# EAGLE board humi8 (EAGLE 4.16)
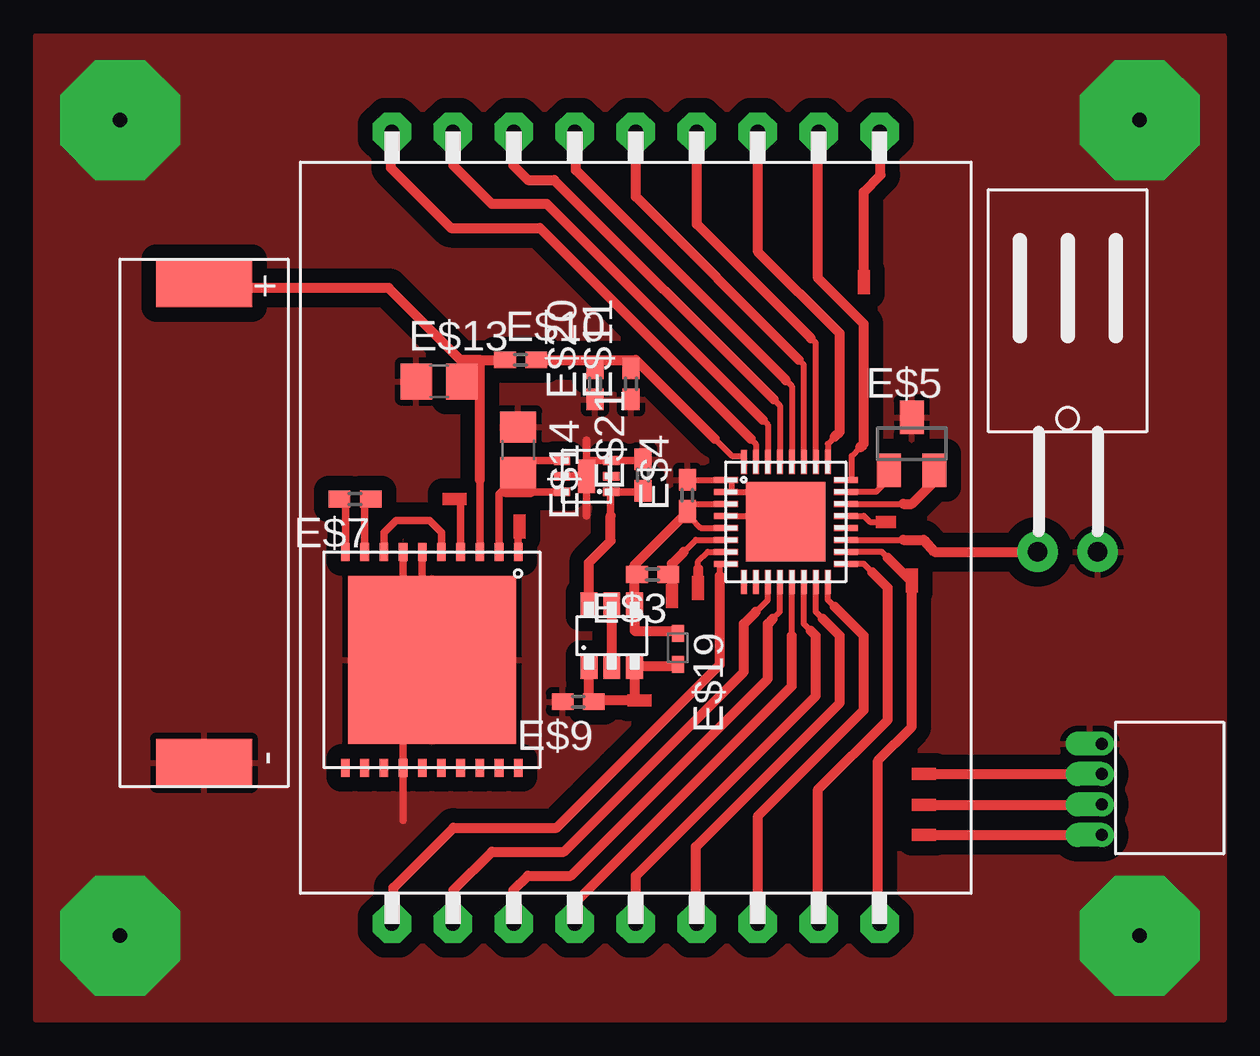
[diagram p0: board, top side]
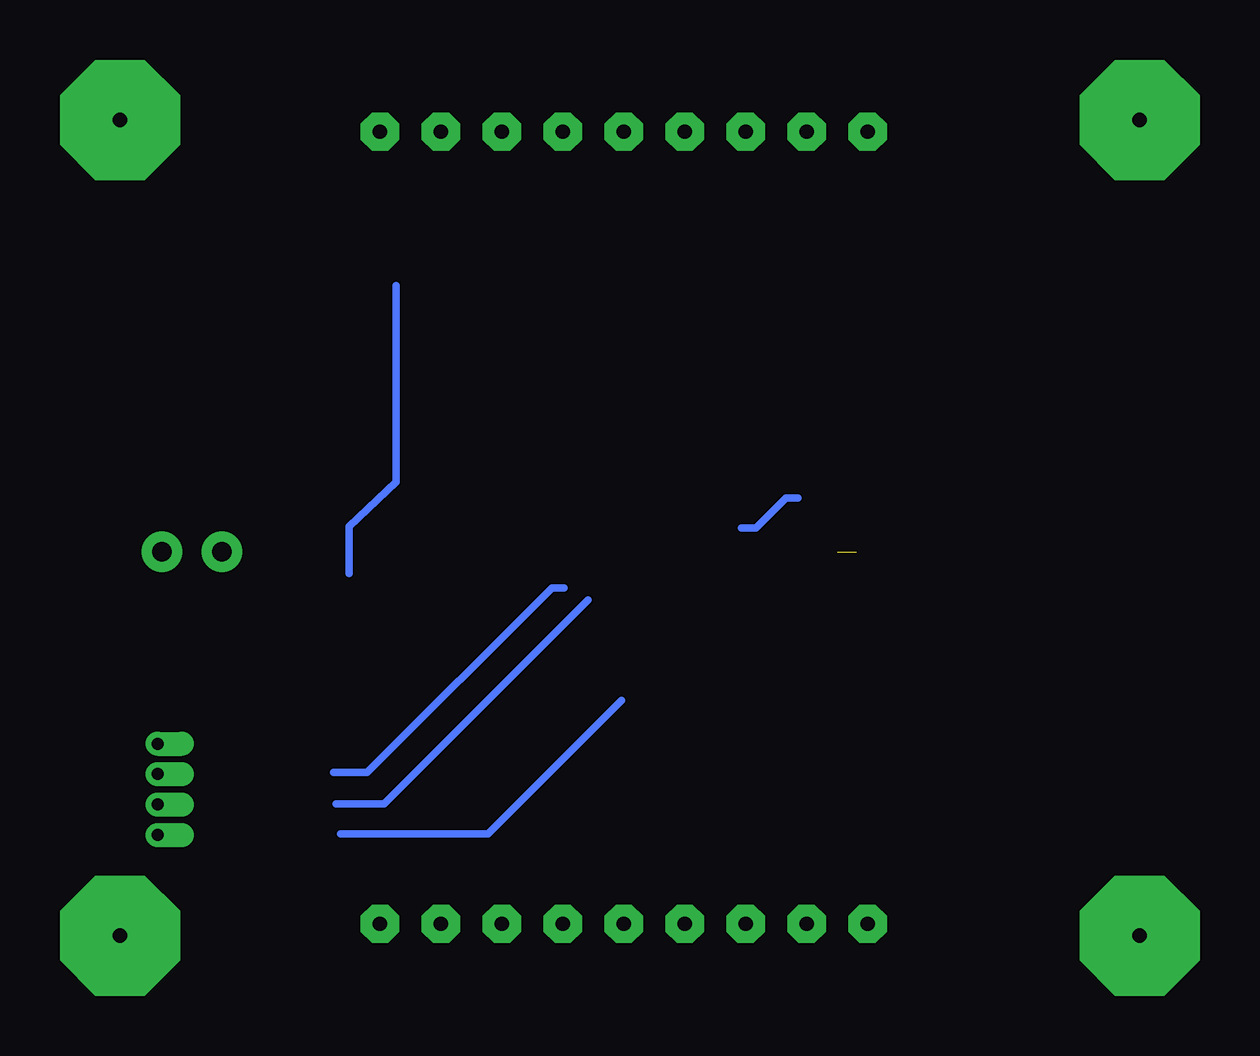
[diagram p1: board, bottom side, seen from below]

No outline drawn. Coordinates in mm, seen from the top.
Copper layers (1*16): Top 0.035mm / dielectric 1.5mm / Bottom 0.035mm
Design rules "default": minimum track width 10mil, minimum drill 24mil, track to track 8mil, track to pad 8mil, pad to pad 8mil, via to via 8mil, smd to smd 8mil, copper to edge 40mil, drill to drill 8mil, minimum pad ring 10mil, minimum via ring 8mil, stop-mask expansion 4mil, vias tented up to drill 0mil, thermal gap 10mil

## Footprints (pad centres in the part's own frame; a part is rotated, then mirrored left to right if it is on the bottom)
QFN32 = smd 1 x 0.25: P$1 -2.25,2; P$2 -2.25,1.5; P$3 -2.25,1; P$4 -2.25,0.5; P$5 -2.25,0; P$6 -2.25,-0.5; P$7 -2.25,-1; P$8 -2.25,-1.5; P$17 2.75,-1.5; P$18 2.75,-1; P$19 2.75,-0.5; P$20 2.75,0; P$21 2.75,0.5; P$22 2.75,1; P$23 2.75,1.5; P$24 2.75,2 | smd 0.25 x 1: P$9 -1.5,-2.25; P$10 -0.5,-2.25; P$11 -1,-2.25; P$12 0,-2.25; P$13 0.5,-2.25; P$14 1,-2.25; P$15 1.5,-2.25; P$16 2,-2.25; P$25 2,2.75; P$26 1.5,2.75; P$27 1,2.75; P$28 0.5,2.75; P$29 0,2.75; P$30 -0.5,2.75; P$31 -1,2.75; P$32 -1.5,2.75 | smd 3.3 x 3.3: P$33 0.25,0.25
VI201 = drill 0.6 pad 1.6 octagon: 1 -10.16,-16.51; 2 -7.62,-16.51; 3 -5.08,-16.51; 4 -2.54,-16.51; 5 0,-16.51; 6 2.54,-16.51; 7 5.08,-16.51; 8 7.62,-16.51; 9 10.16,-16.51; 10 10.16,16.51; 11 7.62,16.51; 12 5.08,16.51; 13 2.54,16.51; 14 0,16.51; 15 -2.54,16.51; 16 -5.08,16.51; 17 -7.62,16.51; 18 -10.16,16.51
R0402 = smd 0.9 x 0.7: 1 -0.65,0; 2 0.65,0
SOT23 = smd 1 x 1.4: 1 -0.95,-1.1; 2 0.95,-1.1; 3 0,1.1
CBC3150 = smd 0.75 x 0.36: P$1 -4.5,-3.6; P$2 -4.5,-2.8; P$3 -4.5,-2; P$4 -4.5,-1.2; P$5 -4.5,-0.4; P$6 -4.5,0.4; P$7 -4.5,1.2; P$8 -4.5,2; P$9 -4.5,2.8; P$10 -4.5,3.6; P$11 4.5,-3.6; P$12 4.5,-2.8; P$13 4.5,-2; P$14 4.5,-1.2; P$15 4.5,-0.4; P$16 4.5,0.4; P$17 4.5,1.2; P$18 4.5,2; P$19 4.5,2.8; P$20 4.5,3.6 | smd 7 x 7: P$21 0,0
6UTDFN = smd 0.68 x 0.36: 1 -1.025,0.65; 2 -1.025,0; 3 -1.025,-0.65; 4 1.025,-0.65; 5 1.025,0; 6 1.025,0.65 | smd 0.71 x 1.4: 7 0,0
KXO22-01X8 = smd 2 x 4: P$1 1,3.5; P$2 21,3.5
C0805 = smd 1.3 x 1.5: 1 -0.95,0; 2 0.95,0
HCH-1000 = drill 0.8 pad 1.676 round: P$1 -1.25,-5; P$2 1.25,-5
HEADER4S_R = drill 0.5 offset: P$1 0,-1.27; P$2 1.27,-1.27; P$3 2.54,-1.27; P$4 3.81,-1.27
SUPERSOT-6 = smd 0.7 x 1: P$1 -0.95,1.3; P$2 0,1.3; P$3 0.95,1.3; P$4 -0.95,-1.3; P$5 0,-1.3; P$6 0.95,-1.3
SOD523 = smd 0.7 x 0.5: A 0.7,0; C -0.6,0

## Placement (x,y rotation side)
E$1  [QFN32]  31,20.5 0 top
E$2  [VI201]  25,20.5 180 top
E$3  [R0402]  25.7,18.55 180 top
E$4  [R0402]  27.15,21.85 90 top
E$5  [SOT23]  36.5,24 0 top
E$6  [CBC3150]  16.5,15 270 top
E$7  [R0402]  13.3,21.7 180 top
E$8  [6UTDFN]  22.95,22.65 180 top
E$9  [R0402]  22.6,13.25 180 top
E$10  [R0402]  20.2,27.5 0 top
E$11  [R0402]  24.8,26.5 90 top
E$12  [KXO22-01X8]  3.5,31.7 270 top
E$13  [C0805]  16.8,26.6 0 top
E$14  [C0805]  20.1,23.75 270 top
E$15  [HCH-1000]  43,24.5 0 top
E$16  [HEADER4S_R]  45.7,11.5 270 top
E$18  [SUPERSOT-6]  24,16 0 top
E$19  [SOD523]  26.75,15.5 270 top
E$20  [R0402]  23.3,26.5 90 top
E$21  [R0402]  25.3,22.7 90 top

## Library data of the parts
E$1 = silabs
E$2 = display-lcd
E$3 E$4 E$7 E$9-E$11 E$13 E$14 E$19-E$21 = ref-packages
E$5 = transistor-fet
E$6 = cymbet
E$8 = maxim
E$12 E$15 E$16 E$18 = sb

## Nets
GND: E$4.2 E$5.3 E$6.P$4 E$6.P$21 E$8.7 E$9.2 E$11.1 E$12.P$2 E$13.1 E$14.1 E$15.P$2 E$16.P$1 E$20.1 E$21.2
S$26: E$6.P$3
S$30: E$6.P$8

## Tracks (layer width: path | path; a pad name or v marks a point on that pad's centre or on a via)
GND  (via drill 0.6 pad 5)  (1 unrouted)
  Top 0.254: E$4.2 28.5,22.5
  Top 0.305: 16,17.9 15.3,17.9 E$6.P$4 | 16.1,19.5 16.1,13.5 15.3,13.5 15.3,8.3 | 22.95,23.3 22.95,24.15 | 22.95,23.3 25.3,23.3 | E$8.7 22.95,21 | E$8.7 22.95,23.3 | 21.95,22.65 E$8.7
  other vias: 3.5,3.5 3.5,37.5 46,3.5 46,37.5
  pour Top (isolate 0.61): 0,0 0,41 49.5,41 49.5,0
PWR
  Top 0.305: 20.65,23.3 21.75,23.3
S$1
  Top 0.254: 33.5,22.5 34,22.5 34,23.5 34.35,23.85
  Top 0.406: 34.35,23.85 34.5,24 34.5,29 32.6,30.9 32.6,37
S$2
  Top 0.254: 28.5,18.5 28.5,19
  Top 0.406: 28.5,18.5 28.5,14.8 21.7,8 17.4,8 14.9,5.5 14.9,4
S$3
  Top 0.305: 13.7,19.7 13.7,21.4
S$4
  Top 0.254: 30.3,25 30.5,24.8 30.5,23.5
  Top 0.406: 17.4,37 17.4,35.6 19,34 21.3,34 30.3,25
S$5
  Top 0.254: 31,23.5 31,25.6 30.75,25.85
  Top 0.406: 30.75,25.85 21.6,35 20.5,35 19.9,35.6 19.9,37.1
S$6
  Top 0.254: 31.5,23.5 31.5,26.4 31.25,26.65
  Top 0.406: 31.25,26.65 22.5,35.4 22.5,37
S$7
  Top 0.254: 32.5,23.5 32.5,28.2 32.3,28.4
  Top 0.406: 32.3,28.4 27.55,33.15 27.55,37
S$8
  Top 0.254: 32,23.5 32,27.3 31.8,27.5
  Top 0.406: 31.8,27.5 25,34.3 25,37
S$9
  Top 0.254: 35.5,19.25 35.25,19.5 34,19.5
  Top 0.406: 35.5,19.25 36.5,18.25
S$10
  Top 0.254: 34.85,18.65 34.5,19 34,19
  Top 0.406: 34.85,18.65 35.5,18 35.5,12.5 32.6,9.6 32.6,4
S$11
  Top 0.254: 32.3,16.2 32,16.5 32,18
  Top 0.406: 32.3,16.2 32.5,16 32.5,13.5 25,6 25,4
S$12
  Top 0.254: 30.5,18 30.5,17.5 30,17
  Top 0.406: 30,17 29.5,16.5 29.5,14.5 22,7 19,7 17.4,5.4 17.4,4
S$13
  Top 0.254: 30.7,16.7 31,17 31,18
  Top 0.406: 30.7,16.7 30.5,16.5 30.5,14.2 22.3,6 20.5,6 19.9,5.4 19.9,4
S$14
  Top 0.254: 31.5,16 31.5,18
  Top 0.406: 31.5,16 31.5,13.9 22.5,4.9 22.5,4
S$15
  Top 0.254: 34,22 35,22 35.5,22.5
S$16
  Top 0.254: 32.8,16.7 32.5,17 32.5,18
  Top 0.406: 32.8,16.7 33.5,16 33.5,13.2 27.5,7.2 27.5,4
S$17
  Top 0.254: 33,18 33,17.5 33.3,17.2
  Top 0.406: 33.3,17.2 34.5,16 34.5,12.9 30.1,8.5 30.1,4
S$18
  Top 0.254: 29,22.5 29,22 30,22
S$19
  Top 0.254: 29,21 30,21
S$20
  Top 0.254: 28.5,20.5 27.7,20.5 27.3,20.9
  Top 0.406: 27.3,20.9 26.9,20.9 24.95,18.95 24.95,17.5
S$21
  Top 0.254: 28.5,20 27.5,20 27,19.5
  Top 0.406: 26.5,17.85 26.5,19 27,19.5
S$22
  Top 0.254: 28.5,19.5 28,19.5 27.6,19.1 27.6,18.8
  Top 0.406: 27.6,18.8 27.6,18
S$23
  Top 0.254: 30,23.5 30,24 29.8,24.2
  Top 0.406: 14.8,37 14.8,35.5 17.3,33 21,33 29.8,24.2
S$24
  Top 0.305: 12.9,19.7 12.9,21.5
S$25
  Top 0.406: 35.1,4 35.1,10.8 36.5,12.2 36.5,18.25
S$26
  Top 0.305: E$6.P$3 14.5,20.3 15,20.8 16.4,20.8 16.9,20.3 16.9,19.5
S$27
  Top 0.254: 34,21.5 36.15,21.5
  Top 0.406: 36.15,21.5 36.5,21.5 37.5,22.5
S$28
  Top 0.305: 17.7,19.8 17.7,21.7
S$29
  Top 0.305: 20.1,19.6 20.1,20.1
S$30
  Top 0.305: E$6.P$8 18.5,22.5
  Top 0.406: 7.5,31 7.5,30.5 14.7,30.5 17.7,27.5 18.5,27.5 | 18.5,22.5 18.5,27.5 | 18.5,27.5 19.5,27.5
S$31
  Top 0.254: 33,23.5 33,24 33.3,24.3
  Top 0.406: 33.3,24.3 33.5,24.5 33.5,28.6 30.1,32 30.1,37
S$32
  Top 0.305: 19.3,19.8 19.3,21.9 19.55,22.15
S$33
  Top 0.406: 24,15 24,17.5
S$34
  Top 0.406: 23.05,14.45 23.05,13.3 24.95,13.3 24.95,14.75 26.8,14.75
S$35
  Top 0.254: 28.3,24.2 29,23.5 29.5,23.5
  Top 0.406: 28.3,24.2 25,27.5 20.9,27.5
S$36
  Top 0.406: 34.5,31.05 34.5,34.5 35.2,35.2 35.2,37
S$37
  Bottom 0.305: 34.5,30.6 34.5,22.4 36.45,20.55 36.45,18.6
S$38
  Bottom 0.305: 17.75,21.75 18.25,21.75 19.5,20.5 20.1,20.5
S$39
  Top 0.254: 34,20 36.15,20
  Top 0.406: 36.15,20 37,20 37.45,19.5 41.75,19.5
S$40
  Top 0.406: 37.15,7.7 43.45,7.7
S$41
  Top 0.406: 37.15,10.25 43.5,10.25
S$42
  Top 0.406: 26.8,16.2 24.95,16.2 24.95,17
S$43
  Top 0.305: 24.1,22 25.5,22
S$44
  Top 0.305: 23.95,21 23.95,22
  Top 0.406: 23.05,17.5 23.05,19.05 23.95,19.95 23.95,21
S$45
  Top 0.254: 27.15,21.5 28.5,21.5
S$46
  Top 0.305: 20.65,22 21.75,22
  Top 0.406: 19.55,22 20.65,22
S$47
  Top 0.406: 37.45,8.95 43.45,8.95
S$48
  Bottom 0.305: 25.1,13.3 30.65,7.75 36.8,7.75
S$49
  Bottom 0.305: 26.5,17.5 35,9 37,9
S$50
  Bottom 0.305: 27.5,18 28,18 35.7,10.3 37.1,10.3
S$51
  Top 0.254: 34,21 34.5,21 34.75,20.75 35.55,20.75
(copper drawn outside any net)
  shapes: Top area x11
